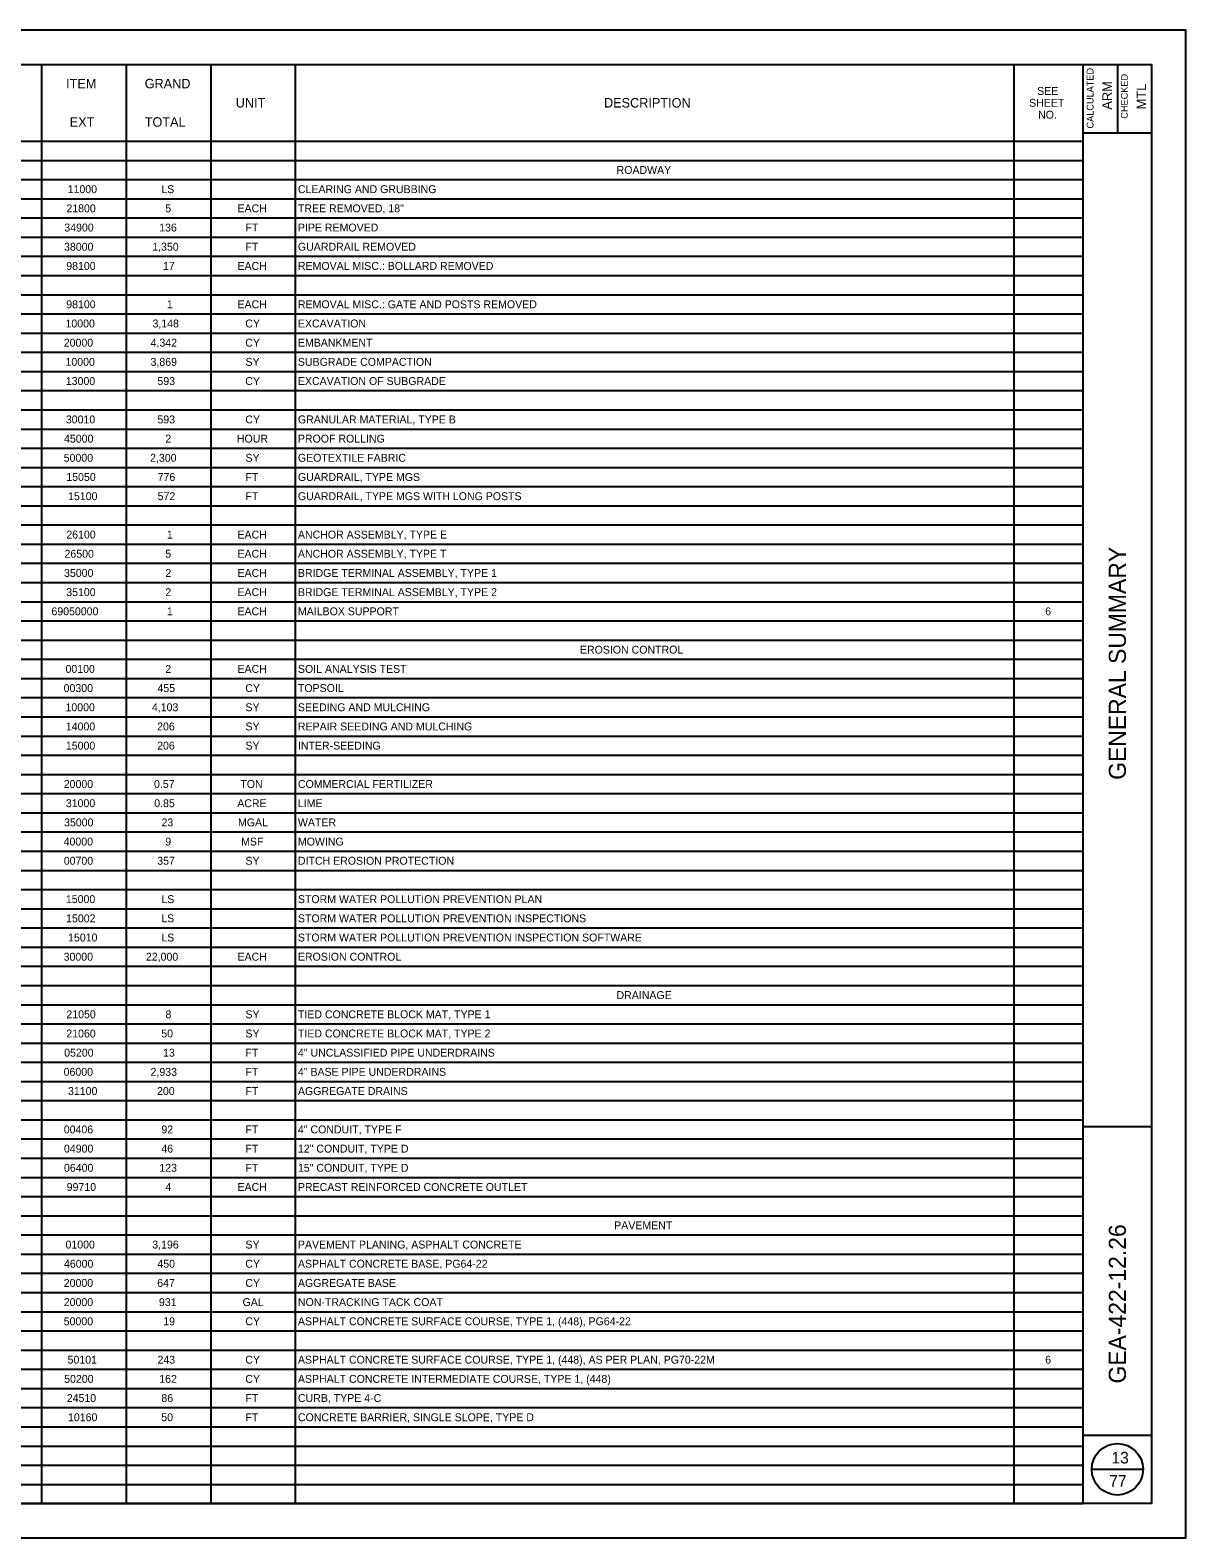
# Model space of a CAD drawing. Extents: x 0 to 34, y 0 to 22.
# Drawn here: x 17.13 to 34, y 0 to 22 of the extents above; entities that cross this region are included whole.
import ezdxf

# ---------------------------------------------------------------- set-up
doc = ezdxf.new("R2010")
doc.units = 0
for name, color, linetype in [('SH_Border', 7, 'Continuous'), ('SH_Cut_Line', 7, 'Continuous'), ('SH_Data', 7, 'Continuous'), ('SH_Text', 7, 'Continuous')]:
    doc.layers.add(name, color=color, linetype=linetype)

msp = doc.modelspace()

# ---------------------------------------------------------------- linework, layer by layer
at = {"layer": 'SH_Border'}
for p, q in [((32.5, 0.5), (32.5, 21.5)), ((33, 21.5), (33, 20.5)), ((32.5, 20.5), (33.5, 20.5)), ((32.5, 6), (33.5, 6)), ((32.5, 1.5), (33.5, 1.5))]:
    msp.add_line(p, q, dxfattribs=at)
msp.add_lwpolyline([(2, 21.5), (33.5, 21.5), (33.5, 0.5), (2, 0.5)], close=True, dxfattribs=at)
at = {"layer": 'SH_Cut_Line'}
msp.add_lwpolyline([(0, 0), (34, 0), (34, 22), (0, 22)], close=True, dxfattribs=at)
at = {"layer": 'SH_Data'}
msp.add_line((32.625, 1), (33.375, 1), dxfattribs=at)
msp.add_circle((33, 1), 0.375, dxfattribs=at)
at = {"layer": 'SH_Text'}
for p, q in [((2, 21.5), (32.5, 21.5)), ((17.299, 0.5), (17.299, 21.5)), ((18.535, 0.5), (18.535, 21.5)), ((19.77, 0.5), (19.77, 21.5)), ((21.005, 0.5), (21.005, 21.5)), ((31.495, 0.5), (31.495, 21.5)), ((32.5, 0.5), (32.5, 21.5)), ((14.055, 20.38), (32.5, 20.38)), ((19.77, 20.38), (32.5, 20.38)), ((2, 20.1), (32.5, 20.1)), ((2, 19.82), (32.5, 19.82)), ((2, 19.54), (32.5, 19.54)), ((2, 19.26), (32.5, 19.26)), ((2, 18.98), (32.5, 18.98)), ((2, 18.7), (32.5, 18.7)), ((2, 18.42), (32.5, 18.42)), ((2, 18.14), (32.5, 18.14)), ((2, 17.86), (32.5, 17.86)), ((2, 17.58), (32.5, 17.58)), ((2, 17.3), (32.5, 17.3)), ((2, 17.02), (32.5, 17.02)), ((2, 16.74), (32.5, 16.74)), ((2, 16.46), (32.5, 16.46)), ((2, 16.18), (32.5, 16.18)), ((2, 15.9), (32.5, 15.9)), ((2, 15.62), (32.5, 15.62)), ((2, 15.34), (32.5, 15.34)), ((2, 15.06), (32.5, 15.06)), ((2, 14.78), (32.5, 14.78)), ((2, 14.5), (32.5, 14.5)), ((2, 14.22), (32.5, 14.22)), ((2, 13.94), (32.5, 13.94)), ((2, 13.66), (32.5, 13.66)), ((2, 13.38), (32.5, 13.38)), ((2, 13.1), (32.5, 13.1)), ((2, 12.82), (32.5, 12.82)), ((2, 12.54), (32.5, 12.54)), ((2, 12.26), (32.5, 12.26)), ((2, 11.98), (32.5, 11.98)), ((2, 11.7), (32.5, 11.7)), ((2, 11.42), (32.5, 11.42)), ((2, 11.14), (32.5, 11.14)), ((2, 10.86), (32.5, 10.86)), ((2, 10.58), (32.5, 10.58)), ((2, 10.3), (32.5, 10.3)), ((2, 10.02), (32.5, 10.02)), ((2, 9.74), (32.5, 9.74)), ((2, 9.46), (32.5, 9.46)), ((2, 9.18), (32.5, 9.18)), ((2, 8.9), (32.5, 8.9)), ((2, 8.62), (32.5, 8.62)), ((2, 8.34), (32.5, 8.34)), ((2, 8.06), (32.5, 8.06)), ((2, 7.78), (32.5, 7.78)), ((2, 7.5), (32.5, 7.5)), ((2, 7.22), (32.5, 7.22)), ((2, 6.94), (32.5, 6.94)), ((2, 6.66), (32.5, 6.66)), ((2, 6.38), (32.5, 6.38)), ((2, 6.1), (32.5, 6.1)), ((2, 5.82), (32.5, 5.82)), ((2, 5.54), (32.5, 5.54)), ((2, 5.26), (32.5, 5.26)), ((2, 4.98), (32.5, 4.98)), ((2, 4.7), (32.5, 4.7)), ((2, 4.42), (32.5, 4.42)), ((2, 4.14), (32.5, 4.14)), ((2, 3.86), (32.5, 3.86)), ((2, 3.58), (32.5, 3.58)), ((2, 3.3), (32.5, 3.3)), ((2, 3.02), (32.5, 3.02)), ((2, 2.74), (32.5, 2.74)), ((2, 2.46), (32.5, 2.46)), ((2, 2.18), (32.5, 2.18)), ((2, 1.9), (32.5, 1.9)), ((2, 1.62), (32.5, 1.62)), ((2, 1.34), (32.5, 1.34)), ((2, 1.06), (32.5, 1.06)), ((2, 0.78), (32.5, 0.78)), ((2, 0.5), (32.5, 0.5))]:
    msp.add_line(p, q, dxfattribs=at)

# ---------------------------------------------------------------- texts
at = {"layer": 'SH_Data'}
for s, height, p in [('CALCULATED', 0.1, (32.652, 20.565)), ('CHECKED', 0.1, (33.152, 20.708)), ('ARM', 0.14, (32.92, 20.84)), ('MTL', 0.14, (33.42, 20.844)), ('GENERAL SUMMARY', 0.25, (33.125, 11.061)), ('GEA-422-12.26', 0.25, (33.125, 2.252))]:
    msp.add_text(s, height=height, rotation=90, dxfattribs=at).set_placement(p)
for s, p in [('13', (32.914, 1.085)), ('77', (32.882, 0.745))]:
    msp.add_text(s, height=0.17, dxfattribs=at).set_placement(p)
at = {"layer": 'SH_Text'}
for s, height, p in [('ITEM', 0.1384, (17.654, 21.151)), ('GRAND', 0.1384, (18.801, 21.151)), ('SEE', 0.1153, (31.83, 21.055)), ('UNIT', 0.1384, (20.13, 20.871)), ('DESCRIPTION', 0.13841, (25.506, 20.871)), ('SHEET', 0.1153, (31.712, 20.882)), ('EXT', 0.1384, (17.707, 20.591)), ('TOTAL', 0.1384, (18.802, 20.591)), ('NO.', 0.1153, (31.843, 20.709)), ('ROADWAY', 0.1153, (25.69, 19.902)), ('11000', 0.1153, (17.677, 19.622)), ('LS', 0.1153, (19.044, 19.622)), ('CLEARING AND GRUBBING ', 0.11534, (21.038, 19.622)), ('21800', 0.1153, (17.658, 19.342)), ('5', 0.115, (19.102, 19.342)), ('EACH', 0.1153, (20.156, 19.342)), ('TREE REMOVED, 18" ', 0.11534, (21.038, 19.342)), ('34900', 0.1153, (17.628, 19.062)), ('136', 0.1153, (19.013, 19.062)), ('FT', 0.1153, (20.272, 19.062)), ('PIPE REMOVED ', 0.11534, (21.038, 19.062)), ('38000', 0.1153, (17.624, 18.782)), ('1,350', 0.1153, (18.911, 18.782)), ('FT', 0.1153, (20.272, 18.782)), ('GUARDRAIL REMOVED ', 0.11534, (21.038, 18.782)), ('98100', 0.1153, (17.656, 18.502)), ('17', 0.1153, (19.068, 18.502)), ('EACH', 0.1153, (20.156, 18.502)), ('REMOVAL MISC.: BOLLARD REMOVED', 0.11534, (21.038, 18.502)), ('98100', 0.1153, (17.656, 17.942)), ('1', 0.115, (19.125, 17.942)), ('EACH', 0.1153, (20.156, 17.942)), ('REMOVAL MISC.: GATE AND POSTS REMOVED', 0.11534, (21.038, 17.942)), ('10000', 0.1153, (17.645, 17.662)), ('3,148', 0.1153, (18.915, 17.662)), ('CY', 0.1153, (20.27, 17.662)), ('EXCAVATION ', 0.11534, (21.038, 17.662)), ('20000', 0.1153, (17.62, 17.382)), ('4,342', 0.1153, (18.887, 17.382)), ('CY', 0.1153, (20.27, 17.382)), ('EMBANKMENT ', 0.11534, (21.038, 17.382)), ('10000', 0.1153, (17.645, 17.102)), ('3,869', 0.1153, (18.887, 17.102)), ('SY', 0.1153, (20.272, 17.102)), ('SUBGRADE COMPACTION ', 0.11534, (21.038, 17.102)), ('13000', 0.1153, (17.65, 16.822)), ('593', 0.1153, (18.987, 16.822)), ('CY', 0.1153, (20.27, 16.822)), ('EXCAVATION OF SUBGRADE ', 0.11534, (21.038, 16.822)), ('30010', 0.1153, (17.65, 16.262)), ('593', 0.1153, (18.987, 16.262)), ('CY', 0.1153, (20.27, 16.262)), ('GRANULAR MATERIAL, TYPE B ', 0.11534, (21.038, 16.262)), ('45000', 0.1153, (17.624, 15.982)), ('2', 0.115, (19.103, 15.982)), ('HOUR', 0.1153, (20.147, 15.982)), ('PROOF ROLLING ', 0.11534, (21.038, 15.982)), ('50000', 0.1153, (17.619, 15.702)), ('2,300', 0.1153, (18.88, 15.702)), ('SY', 0.1153, (20.272, 15.702)), ('GEOTEXTILE FABRIC ', 0.11534, (21.038, 15.702)), ('15050', 0.1153, (17.657, 15.422)), ('776', 0.1153, (18.99, 15.422)), ('FT', 0.1153, (20.272, 15.422)), ('GUARDRAIL, TYPE MGS ', 0.11534, (21.038, 15.422)), ('15100', 0.1153, (17.683, 15.142)), ('572', 0.1153, (18.99, 15.142)), ('FT', 0.1153, (20.272, 15.142)), ('GUARDRAIL, TYPE MGS WITH LONG POSTS ', 0.11534, (21.038, 15.142)), ('26100', 0.1153, (17.657, 14.582)), ('1', 0.115, (19.125, 14.582)), ('EACH', 0.1153, (20.156, 14.582)), ('ANCHOR ASSEMBLY, TYPE E ', 0.11534, (21.038, 14.582)), ('26500', 0.1153, (17.631, 14.302)), ('5', 0.115, (19.102, 14.302)), ('EACH', 0.1153, (20.156, 14.302)), ('ANCHOR ASSEMBLY, TYPE T ', 0.11534, (21.038, 14.302)), ('35000', 0.1153, (17.624, 14.022)), ('2', 0.115, (19.103, 14.022)), ('EACH', 0.1153, (20.156, 14.022)), ('BRIDGE TERMINAL ASSEMBLY, TYPE 1 ', 0.11534, (21.038, 14.022)), ('35100', 0.1153, (17.656, 13.742)), ('2', 0.115, (19.103, 13.742)), ('EACH', 0.1153, (20.156, 13.742)), ('BRIDGE TERMINAL ASSEMBLY, TYPE 2 ', 0.11534, (21.038, 13.742)), ('69050000', 0.1153, (17.44, 13.462)), ('1', 0.115, (19.125, 13.462)), ('EACH', 0.1153, (20.156, 13.462)), ('MAILBOX SUPPORT ', 0.11534, (21.038, 13.462)), ('6', 0.115, (31.947, 13.462)), ('EROSION CONTROL', 0.11534, (25.155, 12.902)), ('00100', 0.1153, (17.645, 12.622)), ('2', 0.115, (19.103, 12.622)), ('EACH', 0.1153, (20.156, 12.622)), ('SOIL ANALYSIS TEST ', 0.11534, (21.038, 12.622)), ('00300', 0.1153, (17.618, 12.342)), ('455', 0.1153, (18.988, 12.342)), ('CY', 0.1153, (20.27, 12.342)), ('TOPSOIL ', 0.1153, (21.038, 12.342)), ('10000', 0.1153, (17.645, 12.062)), ('4,103', 0.1153, (18.907, 12.062)), ('SY', 0.1153, (20.272, 12.062)), ('SEEDING AND MULCHING ', 0.11534, (21.038, 12.062)), ('14000', 0.1153, (17.65, 11.782)), ('206', 0.1153, (18.983, 11.782)), ('SY', 0.1153, (20.272, 11.782)), ('REPAIR SEEDING AND MULCHING ', 0.11534, (21.038, 11.782)), ('15000', 0.1153, (17.651, 11.502)), ('206', 0.1153, (18.983, 11.502)), ('SY', 0.1153, (20.272, 11.502)), ('INTER-SEEDING ', 0.11534, (21.038, 11.502)), ('20000', 0.1153, (17.62, 10.942)), ('0.57', 0.1153, (18.937, 10.942)), ('TON', 0.1153, (20.198, 10.942)), ('COMMERCIAL FERTILIZER ', 0.11534, (21.038, 10.942)), ('31000', 0.1153, (17.65, 10.662)), ('0.85', 0.1153, (18.94, 10.662)), ('ACRE', 0.1153, (20.153, 10.662)), ('LIME ', 0.1153, (21.038, 10.662)), ('35000', 0.1153, (17.624, 10.382)), ('23', 0.1153, (19.046, 10.382)), ('MGAL', 0.1153, (20.163, 10.382)), ('WATER ', 0.1153, (21.038, 10.382)), ('40000', 0.1153, (17.618, 10.102)), ('9', 0.115, (19.102, 10.102)), ('MSF', 0.1153, (20.209, 10.102)), ('MOWING ', 0.1153, (21.038, 10.102)), ('00700', 0.1153, (17.62, 9.822)), ('357', 0.1153, (18.984, 9.822)), ('SY', 0.1153, (20.272, 9.822)), ('DITCH EROSION PROTECTION ', 0.11534, (21.038, 9.822)), ('15000', 0.1153, (17.651, 9.262)), ('LS', 0.1153, (19.044, 9.262)), ('STORM WATER POLLUTION PREVENTION PLAN ', 0.11534, (21.038, 9.262)), ('15002', 0.1153, (17.654, 8.982)), ('LS', 0.1153, (19.044, 8.982)), ('STORM WATER POLLUTION PREVENTION INSPECTIONS', 0.11534, (21.038, 8.982)), ('15010', 0.1153, (17.683, 8.702)), ('LS', 0.1153, (19.044, 8.702)), ('STORM WATER POLLUTION PREVENTION INSPECTION SOFTWARE', 0.11534, (21.038, 8.702)), ('30000', 0.1153, (17.618, 8.422)), ('22,000', 0.1153, (18.819, 8.422)), ('EACH', 0.1153, (20.156, 8.422)), ('EROSION CONTROL ', 0.11534, (21.038, 8.422)), ('DRAINAGE', 0.1153, (25.689, 7.862)), ('21050', 0.1153, (17.658, 7.582)), ('8', 0.115, (19.105, 7.582)), ('SY', 0.1153, (20.272, 7.582)), ('TIED CONCRETE BLOCK MAT, TYPE 1 ', 0.11534, (21.038, 7.582)), ('21060', 0.1153, (17.657, 7.302)), ('50', 0.1153, (19.043, 7.302)), ('SY', 0.1153, (20.272, 7.302)), ('TIED CONCRETE BLOCK MAT, TYPE 2 ', 0.11534, (21.038, 7.302)), ('05200', 0.1153, (17.626, 7.022)), ('13', 0.1153, (19.07, 7.022)), ('FT', 0.1153, (20.272, 7.022)), ('4" UNCLASSIFIED PIPE UNDERDRAINS ', 0.11534, (21.038, 7.022)), ('06000', 0.1153, (17.618, 6.742)), ('2,933', 0.1153, (18.887, 6.742)), ('FT', 0.1153, (20.272, 6.742)), ('4" BASE PIPE UNDERDRAINS ', 0.11534, (21.038, 6.742)), ('31100', 0.1153, (17.682, 6.462)), ('200', 0.1153, (18.981, 6.462)), ('FT', 0.1153, (20.272, 6.462)), ('AGGREGATE DRAINS ', 0.11534, (21.038, 6.462)), ('00406', 0.1153, (17.62, 5.902)), ('92', 0.1153, (19.045, 5.902)), ('FT', 0.1153, (20.272, 5.902)), ('4" CONDUIT, TYPE F ', 0.11534, (21.038, 5.902)), ('04900', 0.1153, (17.623, 5.622)), ('46', 0.1153, (19.044, 5.622)), ('FT', 0.1153, (20.272, 5.622)), ('12" CONDUIT, TYPE D ', 0.11534, (21.038, 5.622)), ('06400', 0.1153, (17.623, 5.342)), ('123', 0.1153, (19.015, 5.342)), ('FT', 0.1153, (20.272, 5.342)), ('15" CONDUIT, TYPE D ', 0.11534, (21.038, 5.342)), ('99710', 0.1153, (17.662, 5.062)), ('4', 0.115, (19.104, 5.062)), ('EACH', 0.1153, (20.156, 5.062)), ('PRECAST REINFORCED CONCRETE OUTLET ', 0.11534, (21.038, 5.062)), ('PAVEMENT', 0.1153, (25.655, 4.502)), ('01000', 0.1153, (17.645, 4.222)), ('3,196', 0.1153, (18.912, 4.222)), ('SY', 0.1153, (20.272, 4.222)), ('PAVEMENT PLANING, ASPHALT CONCRETE ', 0.11534, (21.038, 4.222)), ('46000', 0.1153, (17.623, 3.942)), ('450', 0.1153, (18.986, 3.942)), ('CY', 0.1153, (20.27, 3.942)), ('ASPHALT CONCRETE BASE, PG64-22 ', 0.11534, (21.038, 3.942)), ('20000', 0.1153, (17.62, 3.662)), ('647', 0.1153, (18.984, 3.662)), ('CY', 0.1153, (20.27, 3.662)), ('AGGREGATE BASE ', 0.11534, (21.038, 3.662)), ('20000', 0.1153, (17.62, 3.382)), ('931', 0.1153, (19.009, 3.382)), ('GAL', 0.1153, (20.23, 3.382)), ('NON-TRACKING TACK COAT ', 0.11534, (21.038, 3.382)), ('50000', 0.1153, (17.619, 3.102)), ('19', 0.1153, (19.072, 3.102)), ('CY', 0.1153, (20.27, 3.102)), ('ASPHALT CONCRETE SURFACE COURSE, TYPE 1, (448), PG64-22 ', 0.11534, (21.038, 3.102)), ('50101', 0.1153, (17.676, 2.542)), ('243', 0.1153, (18.988, 2.542)), ('CY', 0.1153, (20.27, 2.542)), ('ASPHALT CONCRETE SURFACE COURSE, TYPE 1, (448), AS PER PLAN, PG70-22M', 0.11534, (21.038, 2.542)), ('6', 0.115, (31.947, 2.542)), ('50200', 0.1153, (17.626, 2.262)), ('162', 0.1153, (19.014, 2.262)), ('CY', 0.1153, (20.27, 2.262)), ('ASPHALT CONCRETE INTERMEDIATE COURSE, TYPE 1, (448) ', 0.11534, (21.038, 2.262)), ('24510', 0.1153, (17.664, 1.982)), ('86', 0.1153, (19.045, 1.982)), ('FT', 0.1153, (20.272, 1.982)), ('CURB, TYPE 4-C ', 0.11534, (21.038, 1.982)), ('10160', 0.1153, (17.682, 1.702)), ('50', 0.1153, (19.043, 1.702)), ('FT', 0.1153, (20.272, 1.702)), ('CONCRETE BARRIER, SINGLE SLOPE, TYPE D ', 0.11534, (21.038, 1.702))]:
    msp.add_text(s, height=height, dxfattribs=at).set_placement(p)

doc.saveas('drawing.dxf')
